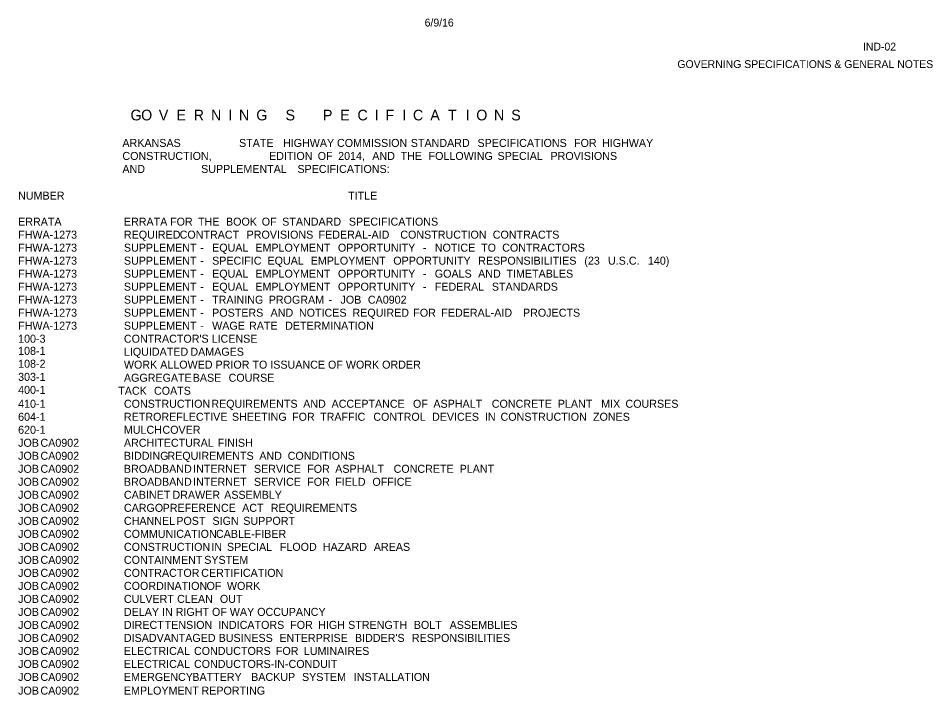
# Model space of a CAD drawing. Extents: x 1226673 to 1228148, y 151313 to 152324.
# Drawn here: x 1227451 to 1228137, y 151817 to 152324 of the extents above; entities that cross this region are included whole.
import ezdxf

# ---------------------------------------------------------------- set-up
doc = ezdxf.new("R2010")
doc.units = 0
doc.layers.add('R_Border', color=7, linetype='Continuous')
doc.layers.add('R_Dimension', color=7, linetype='Continuous')

msp = doc.modelspace()

# ---------------------------------------------------------------- texts
at = {"layer": 'R_Border'}
for s, height, p in [('6/9/16', 5.861, (1227755.88, 152317.55)), ('IND-02', 5.861, (1228084.29, 152299.55)), ('GOVERNING SPECIFICATIONS & GENERAL NOTES ', 5.862, (1227945.27, 152286.45))]:
    msp.add_text(s, height=height, dxfattribs=at).set_placement(p)
at = {"layer": 'R_Dimension'}
for s, height, p in [('G', 8, (1227535.54, 152247.19)), (' O', 8, (1227540.51, 152247.19)), (' V', 8, (1227553.74, 152247.19)), (' E', 8, (1227566.97, 152247.19)), (' R', 8, (1227579.88, 152247.19)), (' N', 8, (1227592.86, 152247.19)), (' I', 8, (1227605.83, 152247.19)), (' N', 8, (1227613.83, 152247.19)), (' G', 8, (1227626.81, 152247.19)), ('    S', 8, (1227639.79, 152247.19)), (' P', 8, (1227676.7, 152247.19)), (' E', 8, (1227689.68, 152247.19)), (' C', 8, (1227702.59, 152247.19)), (' I', 8, (1227715.57, 152247.19)), (' F', 8, (1227723.57, 152247.19)), (' I', 8, (1227736.17, 152247.19)), (' C', 8, (1227744.17, 152247.19)), (' A', 8, (1227757.14, 152247.19)), (' T', 8, (1227770.37, 152247.19)), (' I', 8, (1227783.6, 152247.19)), (' O', 8, (1227791.6, 152247.19)), (' N', 8, (1227804.83, 152247.19)), (' S', 8, (1227817.8, 152247.19)), ('           ARKANSAS', 6, (1227504.94, 152227.29)), (' STATE', 6, (1227614.6, 152227.29)), (' HIGHWAY', 6, (1227647.53, 152227.29)), (' COMMISSION', 6, (1227688.02, 152227.29)), (' STANDARD', 6, (1227743.29, 152227.29)), (' SPECIFICATIONS', 6, (1227793.28, 152227.29)), (' FOR', 6, (1227865.61, 152227.29)), (' HIGHWAY', 6, (1227886.58, 152227.29)), ('           CONSTRUCTION,', 6, (1227504.94, 152217.54)), (' EDITION', 6, (1227637.09, 152217.54)), (' OF', 6, (1227673.56, 152217.54)), (' 2014,', 6, (1227688.87, 152217.54)), (' AND', 6, (1227714.43, 152217.54)), (' THE', 6, (1227735.68, 152217.54)), (' FOLLOWING', 6, (1227756.61, 152217.54)), (' SPECIAL', 6, (1227808.3, 152217.54)), (' PROVISIONS', 6, (1227847.94, 152217.54)), ('           AND', 6, (1227504.94, 152207.79)), (' SUPPLEMENTAL', 6, (1227586.2, 152207.79)), (' SPECIFICATIONS:', 6, (1227658.35, 152207.79)), ('NUMBER', 6, (1227451.32, 152187.8)), ('TITLE', 6, (1227698.55, 152187.8)), ('ERRATA', 6, (1227451.32, 152168.3)), ('ERRATA', 6, (1227530.58, 152168.3)), (' FOR', 6, (1227562.94, 152168.3)), (' THE', 6, (1227583.91, 152168.3)), (' BOOK', 6, (1227604.84, 152168.3)), (' OF', 6, (1227631.63, 152168.3)), (' STANDARD', 6, (1227646.94, 152168.3)), (' SPECIFICATIONS', 6, (1227696.92, 152168.3)), ('FHWA-1273', 6, (1227451.32, 152158.55)), ('REQUIRED', 6, (1227530.58, 152158.55)), (' CONTRACT', 6, (1227570.12, 152158.55)), (' PROVISIONS', 6, (1227620.29, 152158.55)), (' FEDERAL-AID', 6, (1227674.2, 152158.55)), (' CONSTRUCTION', 6, (1227735.43, 152158.55)), (' CONTRACTS', 6, (1227804.69, 152158.55)), ('FHWA-1273', 6, (1227451.32, 152148.8)), ('SUPPLEMENT', 6, (1227530.58, 152148.8)), (' -', 6, (1227585.52, 152148.8)), (' EQUAL', 6, (1227594.45, 152148.8)), (' EMPLOYMENT', 6, (1227626.81, 152148.8)), (' OPPORTUNITY', 6, (1227688.7, 152148.8)), (' -', 6, (1227752.34, 152148.8)), (' NOTICE', 6, (1227761.27, 152148.8)), (' TO', 6, (1227795.99, 152148.8)), (' CONTRACTORS', 6, (1227811.77, 152148.8)), ('FHWA-1273', 6, (1227451.32, 152139.05)), ('SUPPLEMENT', 6, (1227530.58, 152139.05)), (' SPECIFIC', 6, (1227594.45, 152139.05)), (' EQUAL', 6, (1227635.93, 152139.05)), (' EMPLOYMENT', 6, (1227668.29, 152139.05)), (' OPPORTUNITY', 6, (1227730.18, 152139.05)), (' RESPONSIBILITIES', 6, (1227793.82, 152139.05)), (' (23', 6, (1227873.33, 152139.05)), (' U.S.C.', 6, (1227891.05, 152139.05)), (' 140)', 6, (1227920.95, 152139.05)), (' -', 6, (1227585.52, 152139.05)), ('FHWA-1273', 6, (1227451.32, 152129.3)), ('SUPPLEMENT', 6, (1227530.58, 152129.3)), (' -', 6, (1227585.52, 152129.3)), (' EQUAL', 6, (1227594.45, 152129.3)), (' EMPLOYMENT', 6, (1227626.81, 152129.3)), (' OPPORTUNITY', 6, (1227688.7, 152129.3)), (' -', 6, (1227752.34, 152129.3)), (' GOALS', 6, (1227761.27, 152129.3)), (' AND', 6, (1227793.73, 152129.3)), (' TIMETABLES', 6, (1227814.99, 152129.3)), ('FHWA-1273', 6, (1227451.32, 152119.55)), ('SUPPLEMENT', 6, (1227530.58, 152119.55)), (' EQUAL', 6, (1227594.45, 152119.55)), (' EMPLOYMENT', 6, (1227626.81, 152119.55)), (' OPPORTUNITY', 6, (1227688.7, 152119.55)), (' FEDERAL', 6, (1227761.27, 152119.55)), (' STANDARDS', 6, (1227804.03, 152119.55)), (' -', 6, (1227585.52, 152119.55)), (' -', 6, (1227752.34, 152119.55)), ('FHWA-1273', 6, (1227451.32, 152109.8)), ('SUPPLEMENT', 6, (1227530.58, 152109.8)), (' -', 6, (1227585.52, 152109.8)), (' TRAINING', 6, (1227594.45, 152109.8)), (' PROGRAM', 6, (1227636.88, 152109.8)), (' -', 6, (1227681.71, 152109.8)), (' JOB', 6, (1227690.64, 152109.8)), (' CA0902', 6, (1227711.14, 152109.8)), ('FHWA-1273', 6, (1227451.32, 152100.05)), ('SUPPLEMENT', 6, (1227530.58, 152100.05)), (' -', 6, (1227585.52, 152100.05)), (' POSTERS', 6, (1227594.45, 152100.05)), (' AND', 6, (1227638.25, 152100.05)), (' NOTICES', 6, (1227659.51, 152100.05)), (' REQUIRED', 6, (1227699.62, 152100.05)), (' FOR', 6, (1227745.16, 152100.05)), (' FEDERAL-AID', 6, (1227766.14, 152100.05)), (' PROJECTS', 6, (1227827.36, 152100.05)), ('FHWA-1273', 6, (1227451.32, 152090.3)), ('SUPPLEMENT', 6, (1227530.58, 152090.3)), (' WAGE', 6, (1227594.45, 152090.3)), (' RATE', 6, (1227622.09, 152090.3)), (' DETERMINATION', 6, (1227649.16, 152090.3)), (' -', 6, (1227585.52, 152090.3)), ('100-3', 6, (1227451.32, 152080.55)), ("CONTRACTOR'S LICENSE", 6, (1227530.58, 152080.55)), ('108-1', 6, (1227451.32, 152071.47)), ('LIQUIDATED', 6, (1227530.58, 152070.8)), (' DAMAGES', 6, (1227578.15, 152070.8)), ('108-2', 6, (1227451.32, 152061.8)), ('WORK ALLOWED PRIOR TO ISSUANCE OF WORK ORDER', 6, (1227530.58, 152061.12)), ('303-1', 6, (1227451.32, 152051.97)), ('AGGREGATE', 6, (1227530.58, 152051.3)), (' BASE', 6, (1227579.9, 152051.3)), (' COURSE', 6, (1227606.78, 152051.3)), ('400-1', 6, (1227451.32, 152042.22)), (' TACK', 6, (1227524.1, 152041.55)), (' COATS', 6, (1227550.89, 152041.55)), ('410-1', 6, (1227451.32, 152031.8)), ('CONSTRUCTION', 6, (1227530.58, 152031.8)), (' REQUIREMENTS', 6, (1227593.84, 152031.8)), (' AND', 6, (1227662.67, 152031.8)), (' ACCEPTANCE', 6, (1227683.93, 152031.8)), (' OF', 6, (1227744.92, 152031.8)), (' ASPHALT', 6, (1227760.23, 152031.8)), (' CONCRETE', 6, (1227803.98, 152031.8)), (' PLANT', 6, (1227853.44, 152031.8)), (' MIX', 6, (1227885.95, 152031.8)), (' COURSES', 6, (1227904.14, 152031.8)), ('604-1', 6, (1227451.32, 152022.05)), ('RETROREFLECTIVE', 6, (1227530.58, 152022.05)), (' SHEETING', 6, (1227609.29, 152022.05)), (' FOR', 6, (1227654.36, 152022.05)), (' TRAFFIC', 6, (1227675.33, 152022.05)), (' CONTROL', 6, (1227715.21, 152022.05)), (' DEVICES', 6, (1227759.19, 152022.05)), (' IN', 6, (1227798.83, 152022.05)), (' CONSTRUCTION', 6, (1227810.54, 152022.05)), (' ZONES', 6, (1227879.8, 152022.05)), ('620-1', 6, (1227451.32, 152012.3)), ('MULCH', 6, (1227530.58, 152012.3)), (' COVER', 6, (1227557.22, 152012.3)), ('JOB', 6, (1227451.32, 152002.55)), (' CA0902', 6, (1227465.82, 152002.55)), ('ARCHITECTURAL', 6, (1227530.58, 152002.55)), (' FINISH', 6, (1227598.61, 152002.55)), ('JOB', 6, (1227451.32, 151992.8)), (' CA0902', 6, (1227465.82, 151992.8)), ('BIDDING', 6, (1227530.58, 151992.8)), (' REQUIREMENTS', 6, (1227560.95, 151992.8)), (' AND', 6, (1227629.79, 151992.8)), (' CONDITIONS', 6, (1227651.05, 151992.8)), ('JOB', 6, (1227451.32, 151983.05)), (' CA0902', 6, (1227465.82, 151983.05)), ('BROADBAND', 6, (1227530.58, 151983.05)), (' INTERNET', 6, (1227580.23, 151983.05)), (' SERVICE', 6, (1227625.77, 151983.05)), (' FOR', 6, (1227665.69, 151983.05)), (' ASPHALT', 6, (1227686.67, 151983.05)), (' CONCRETE', 6, (1227730.42, 151983.05)), (' PLANT', 6, (1227779.88, 151983.05)), ('JOB', 6, (1227451.32, 151973.3)), (' CA0902', 6, (1227465.82, 151973.3)), ('BROADBAND', 6, (1227530.58, 151973.3)), (' INTERNET', 6, (1227580.23, 151973.3)), (' SERVICE', 6, (1227625.77, 151973.3)), (' FOR', 6, (1227665.69, 151973.3)), (' FIELD', 6, (1227686.67, 151973.3)), (' OFFICE', 6, (1227714.54, 151973.3)), ('JOB', 6, (1227451.32, 151963.55)), (' CA0902', 6, (1227465.82, 151963.55)), ('CABINET', 6, (1227530.58, 151963.55)), (' DRAWER', 6, (1227564.73, 151963.55)), (' ASSEMBLY', 6, (1227603.47, 151963.55)), ('JOB', 6, (1227451.32, 151953.8)), (' CA0902', 6, (1227465.82, 151953.8)), ('CARGO', 6, (1227530.58, 151953.8)), (' PREFERENCE', 6, (1227557.36, 151953.8)), (' ACT', 6, (1227616.94, 151953.8)), (' REQUIREMENTS', 6, (1227638.39, 151953.8)), ('JOB', 6, (1227451.32, 151944.05)), (' CA0902', 6, (1227465.82, 151944.05)), ('CHANNEL', 6, (1227530.58, 151944.05)), (' POST', 6, (1227567.62, 151944.05)), (' SIGN', 6, (1227594.73, 151944.05)), (' SUPPORT', 6, (1227617.79, 151944.05)), ('JOB', 6, (1227451.32, 151934.3)), (' CA0902', 6, (1227465.82, 151934.3)), ('COMMUNICATION', 6, (1227530.58, 151934.3)), (' CABLE-FIBER', 6, (1227597.33, 151934.3)), ('JOB', 6, (1227451.32, 151924.55)), (' CA0902', 6, (1227465.82, 151924.55)), ('CONSTRUCTION', 6, (1227530.58, 151924.55)), (' IN', 6, (1227593.84, 151924.55)), (' SPECIAL', 6, (1227605.55, 151924.55)), (' FLOOD', 6, (1227645.19, 151924.55)), (' HAZARD', 6, (1227677.41, 151924.55)), (' AREAS', 6, (1227715.58, 151924.55)), ('JOB', 6, (1227451.32, 151914.8)), (' CA0902', 6, (1227465.82, 151914.8)), ('CONTAINMENT', 6, (1227530.58, 151914.8)), (' SYSTEM', 6, (1227588.54, 151914.8)), ('JOB', 6, (1227451.32, 151905.05)), (' CA0902', 6, (1227465.82, 151905.05)), ('CONTRACTOR', 6, (1227530.58, 151905.05)), (' CERTIFICATION', 6, (1227586.28, 151905.05)), ('JOB', 6, (1227451.32, 151895.3)), (' CA0902', 6, (1227465.82, 151895.3)), ('COORDINATION', 6, (1227530.58, 151895.3)), (' OF', 6, (1227590.25, 151895.3)), (' WORK', 6, (1227605.55, 151895.3)), ('JOB', 6, (1227451.32, 151885.55)), (' CA0902', 6, (1227465.82, 151885.55)), ('CULVERT', 6, (1227530.58, 151885.55)), (' CLEAN', 6, (1227568.23, 151885.55)), (' OUT', 6, (1227600.26, 151885.55)), ('JOB', 6, (1227451.32, 151875.8)), (' CA0902', 6, (1227465.82, 151875.8)), ('DELAY IN RIGHT OF WAY OCCUPANCY', 6, (1227530.58, 151875.8)), ('JOB', 6, (1227451.32, 151866.05)), (' CA0902', 6, (1227465.82, 151866.05)), ('DIRECT', 6, (1227530.58, 151866.05)), (' TENSION', 6, (1227558.88, 151866.05)), (' INDICATORS', 6, (1227599.03, 151866.05)), (' FOR', 6, (1227652.94, 151866.05)), (' HIGH', 6, (1227673.91, 151866.05)), (' STRENGTH', 6, (1227696.36, 151866.05)), (' BOLT', 6, (1227745.54, 151866.05)), (' ASSEMBLIES', 6, (1227772.37, 151866.05)), ('JOB', 6, (1227451.32, 151856.3)), (' CA0902', 6, (1227465.82, 151856.3)), ('DISADVANTAGED', 6, (1227530.58, 151856.3)), (' BUSINESS', 6, (1227599.32, 151856.3)), (' ENTERPRISE', 6, (1227644.81, 151856.3)), (" BIDDER'S", 6, (1227701.46, 151856.3)), (' RESPONSIBILITIES', 6, (1227744.12, 151856.3)), ('JOB', 6, (1227451.32, 151846.55)), (' CA0902', 6, (1227465.82, 151846.55)), ('ELECTRICAL', 6, (1227530.58, 151846.55)), (' CONDUCTORS', 6, (1227580.84, 151846.55)), (' FOR', 6, (1227642.21, 151846.55)), (' LUMINAIRES', 6, (1227663.19, 151846.55)), ('JOB', 6, (1227451.32, 151836.8)), (' CA0902', 6, (1227465.82, 151836.8)), ('ELECTRICAL', 6, (1227530.58, 151836.8)), (' CONDUCTORS-IN-CONDUIT', 6, (1227580.84, 151836.8)), ('JOB', 6, (1227451.32, 151827.05)), (' CA0902', 6, (1227465.82, 151827.05)), ('EMERGENCY', 6, (1227530.58, 151827.05)), (' BATTERY', 6, (1227579.62, 151827.05)), (' BACKUP', 6, (1227623.69, 151827.05)), (' SYSTEM', 6, (1227661.77, 151827.05)), (' INSTALLATION', 6, (1227700.56, 151827.05)), ('JOB', 6, (1227451.32, 151816.81)), (' CA0902', 6, (1227465.82, 151816.81)), ('EMPLOYMENT', 6, (1227530.58, 151816.81)), (' REPORTING', 6, (1227586.47, 151816.81))]:
    msp.add_text(s, height=height, dxfattribs=at).set_placement(p)

doc.saveas('drawing.dxf')
